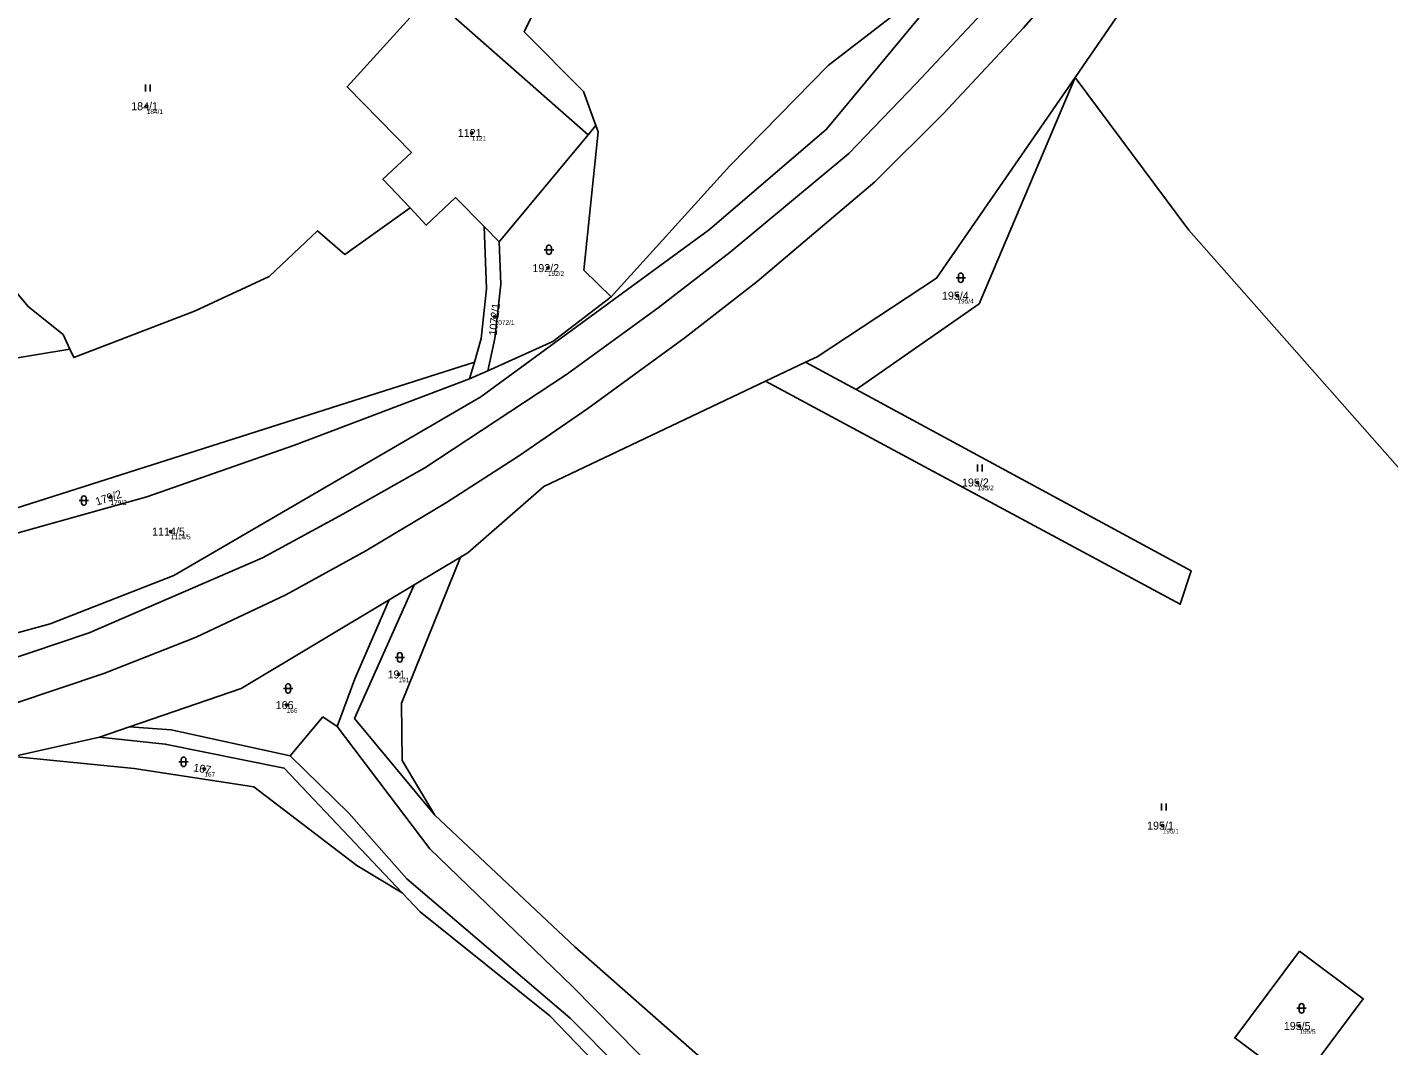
# Model space of a CAD drawing. Extents: x -554500 to -548272, y -1079733 to -1073730.
# Drawn here: x -552544.1 to -552254.7, y -1077027.7 to -1076811.2 of the extents above; entities that cross this region are included whole.
import ezdxf

# ---------------------------------------------------------------- set-up
doc = ezdxf.new("R2010")
doc.units = 0
for name, color, linetype in [('Definiční body', 7, 'Continuous'), ('Hranice parcel', 7, 'Continuous'), ('Parcelní čísla', 7, 'Continuous'), ('Polygon parcely', 7, 'Continuous'), ('Vnitřní kresba', 7, 'Continuous'), ('Značky kultur', 7, 'Continuous')]:
    doc.layers.add(name, color=color, linetype=linetype)

msp = doc.modelspace()

# ---------------------------------------------------------------- linework, layer by layer
at = {"layer": 'Definiční body'}
for centre in [(-552518.66, -1076828.01994), (-552449.6, -1076833.69994), (-552433.42, -1076862.42994), (-552346.39, -1076868.28994), (-552444.74, -1076872.83994), (-552342.14, -1076907.99994), (-552526.36, -1076911.08994), (-552513.57, -1076918.41994), (-552465.15, -1076948.79994), (-552488.94, -1076955.29994), (-552506.43, -1076968.89994), (-552302.8, -1076980.93994), (-552273.75, -1077023.50994)]:
    msp.add_circle(centre, 0.25, dxfattribs=at)
at = {"layer": 'Hranice parcel'}
for p, q in [((-552457.08, -1076805.77), (-552424.83, -1076834.09)), ((-552310.33, -1076805.85), (-552321.39, -1076821.89)), ((-552424.83, -1076834.09), (-552443.81, -1076856.81)), ((-552424.83, -1076834.09), (-552423.2, -1076832.14)), ((-552443.81, -1076856.81), (-552446.97, -1076853.59)), ((-552450.05, -1076885.97), (-552449.01, -1076882.39)), ((-552378.65, -1076882.43), (-552387.19, -1076886.49)), ((-552367.9, -1076888.25), (-552378.65, -1076882.43)), ((-552450.05, -1076885.97), (-552446.18, -1076884.23)), ((-552452, -1076923.9), (-552461.81, -1076929.78)), ((-552461.81, -1076929.78), (-552467.13, -1076932.97)), ((-552522.34, -1076959.95), (-552528.73, -1076962.14)), ((-552528.73, -1076962.14), (-552547.07, -1076966.24))]:
    msp.add_line(p, q, dxfattribs=at)
for points in [[(-552438.83, -1076776.9), (-552426.06, -1076787.21), (-552438.43, -1076812.18), (-552425.84, -1076824.91), (-552423.2, -1076832.14)], [(-552346.57, -1076799.53), (-552374.22, -1076832.9), (-552399.11, -1076854.21), (-552447.65, -1076889.79), (-552512.89, -1076927.79), (-552539.21, -1076938.07), (-552603.07, -1076955.53), (-552606.91, -1076952.69)], [(-552419.95, -1076868.56), (-552394.79, -1076840.7), (-552373.9, -1076819.35), (-552350.45, -1076801.2), (-552346.57, -1076799.53)], [(-552457.08, -1076805.77), (-552458.51, -1076804.49), (-552476.08, -1076823.93), (-552462.42, -1076837.85), (-552468.46, -1076843.54), (-552462.72, -1076849.65)], [(-552321.39, -1076821.89), (-552350.83, -1076864.58), (-552376.22, -1076881.28), (-552378.65, -1076882.43)], [(-552321.39, -1076821.89), (-552341.81, -1076870.01), (-552367.9, -1076888.25)], [(-552214.47, -1076946.82), (-552224.62, -1076936.61), (-552297.2, -1076854.34), (-552321.39, -1076821.89)], [(-552423.2, -1076832.14), (-552422.71, -1076833.48), (-552425.8, -1076862.86), (-552419.95, -1076868.56)], [(-552446.97, -1076853.59), (-552453.02, -1076847.43), (-552459.27, -1076853.31), (-552462.72, -1076849.65)], [(-552462.72, -1076849.65), (-552476.59, -1076859.51), (-552482.38, -1076854.49), (-552492.64, -1076864.2), (-552508.52, -1076871.6), (-552534.18, -1076881.44), (-552534.99, -1076879.69)], [(-552534.99, -1076879.69), (-552536.45, -1076876.51), (-552543.75, -1076870.63), (-552557.16, -1076854.73), (-552574.74, -1076858.68)], [(-552449.01, -1076882.39), (-552447.57, -1076877.4), (-552446.49, -1076866.82), (-552446.97, -1076853.59)], [(-552443.81, -1076856.81), (-552443.41, -1076865.86), (-552444.67, -1076877.42), (-552446.18, -1076884.23)], [(-552446.18, -1076884.23), (-552432.39, -1076878.02), (-552419.95, -1076868.56)], [(-552534.99, -1076879.69), (-552565.54, -1076884.7), (-552574.31, -1076892.6), (-552596.73, -1076899.68), (-552610.12, -1076910.54), (-552662.95, -1076932.83), (-552671.9, -1076938.83)], [(-552612.05, -1076948.89), (-552568.93, -1076920.59), (-552449.01, -1076882.39)], [(-552606.91, -1076952.69), (-552587.97, -1076938.97), (-552565.62, -1076924.94), (-552556.21, -1076921.51), (-552518.61, -1076911.04), (-552487.29, -1076900.06), (-552450.05, -1076885.97)], [(-552387.19, -1076886.49), (-552434.3, -1076908.86), (-552450.44, -1076922.96), (-552452, -1076923.9)], [(-552367.9, -1076888.25), (-552296.74, -1076926.75), (-552299.06, -1076933.88), (-552387.19, -1076886.49)], [(-552457.43, -1076978.68), (-552464.37, -1076967.12), (-552464.53, -1076954.93), (-552452, -1076923.9)], [(-552461.81, -1076929.78), (-552474.5, -1076958.16), (-552457.43, -1076978.68)], [(-552467.13, -1076932.97), (-552498.59, -1076951.8), (-552522.34, -1076959.95)], [(-552478.23, -1076959.85), (-552474.45, -1076949.72), (-552467.13, -1076932.97)], [(-552488.18, -1076966.12), (-552481.23, -1076957.82), (-552478.23, -1076959.85)], [(-552522.34, -1076959.95), (-552513.47, -1076960.55), (-552488.18, -1076966.12)], [(-552003.16, -1077148.87), (-552066.45, -1077133.87), (-552097.39, -1077132.02), (-552117.4, -1077128.2), (-552162.68, -1077124.75), (-552183.65, -1077121.42), (-552235.84, -1077136.49), (-552278.25, -1077120.77), (-552291.51, -1077117.04), (-552315.43, -1077100.3), (-552359.93, -1077070.34), (-552386.3, -1077053.18), (-552404.96, -1077038.74), (-552428.17, -1077015.12), (-552458.54, -1076985.87), (-552478.23, -1076959.85)], [(-552464.37, -1076995.19), (-552489.45, -1076968.7), (-552514.74, -1076963.59), (-552528.73, -1076962.14)], [(-552547.07, -1076966.24), (-552521.34, -1076968.79), (-552495.87, -1076972.7), (-552473.99, -1076989.37), (-552464.37, -1076995.19)], [(-552488.18, -1076966.12), (-552475.72, -1076978.25), (-552463.39, -1076992.24), (-552428.7, -1077021.87), (-552407.66, -1077043.02), (-552379.69, -1077065.86), (-552347.28, -1077090.35), (-552309.72, -1077113.73), (-552291.24, -1077129.35), (-552235.83, -1077188.41), (-552210.35, -1077214.27), (-552151.33, -1077261.82)], [(-552457.43, -1076978.68), (-552427.73, -1077006.67), (-552392.11, -1077037.99), (-552378.85, -1077048.33), (-552297.05, -1077103.87)], [(-552260.41, -1077166.05), (-552293.39, -1077130.79), (-552310.87, -1077116.37), (-552352.02, -1077090.37), (-552410.63, -1077044.59), (-552433.01, -1077021.34), (-552460.53, -1076999.25), (-552464.37, -1076995.19)], [(-552273.72, -1077007.61), (-552260.16, -1077017.73), (-552273.91, -1077036.17), (-552287.48, -1077026.04), (-552273.72, -1077007.61)]]:
    msp.add_lwpolyline(points, dxfattribs=at)
at = {"layer": 'Polygon parcely'}
for points in [[(-551999.3, -1076526.07), (-552010.87, -1076527.63), (-552069.7, -1076539.42), (-552133.32, -1076566.09), (-552182.66, -1076602.14), (-552190.26, -1076610.7), (-552192.81, -1076613.57), (-552196.25, -1076617.44), (-552232.91, -1076658.76), (-552278.63, -1076708.6), (-552281.34, -1076714.84), (-552283.97, -1076720.95), (-552309.19, -1076755.85), (-552313.73, -1076761.03), (-552315.85, -1076763.45), (-552328.64, -1076778.02), (-552330.5, -1076780.14), (-552346.57, -1076799.53), (-552374.22, -1076832.9), (-552399.11, -1076854.21), (-552447.65, -1076889.79), (-552512.89, -1076927.79), (-552539.21, -1076938.07), (-552603.07, -1076955.53)], [(-552557.16, -1076854.73), (-552543.75, -1076870.63), (-552536.45, -1076876.51), (-552534.99, -1076879.69), (-552534.18, -1076881.44), (-552508.52, -1076871.6), (-552492.64, -1076864.2), (-552482.38, -1076854.49), (-552476.59, -1076859.51), (-552462.72, -1076849.65), (-552468.46, -1076843.54), (-552462.42, -1076837.85), (-552476.08, -1076823.93), (-552458.51, -1076804.49), (-552457.08, -1076805.77), (-552455.1, -1076802.88), (-552484.74, -1076783.52), (-552486.79, -1076785.42), (-552511.86, -1076786.78), (-552529.93, -1076790.39), (-552540.74, -1076796.32), (-552547.51, -1076797)], [(-552547.07, -1076966.24), (-552528.73, -1076962.14), (-552522.34, -1076959.95), (-552498.59, -1076951.8), (-552467.13, -1076932.97), (-552461.81, -1076929.78), (-552452, -1076923.9), (-552450.44, -1076922.96), (-552434.3, -1076908.86), (-552387.19, -1076886.49), (-552378.65, -1076882.43), (-552376.22, -1076881.28), (-552350.83, -1076864.58), (-552321.39, -1076821.89), (-552310.33, -1076805.85)], [(-552095.22, -1077044.76), (-552139.39, -1077015.91), (-552159.33, -1077012.39), (-552166.13, -1077004.81), (-552214.47, -1076946.82), (-552224.62, -1076936.61), (-552297.2, -1076854.34), (-552321.39, -1076821.89), (-552341.81, -1076870.01), (-552367.9, -1076888.25), (-552296.74, -1076926.75), (-552299.06, -1076933.88), (-552387.19, -1076886.49), (-552434.3, -1076908.86), (-552450.44, -1076922.96), (-552452, -1076923.9), (-552464.53, -1076954.93), (-552464.37, -1076967.12), (-552457.43, -1076978.68), (-552427.73, -1077006.67), (-552392.11, -1077037.99)], [(-552568.93, -1076920.59), (-552449.01, -1076882.39), (-552447.57, -1076877.4), (-552446.49, -1076866.82), (-552446.97, -1076853.59), (-552453.02, -1076847.43), (-552459.27, -1076853.31), (-552462.72, -1076849.65), (-552476.59, -1076859.51), (-552482.38, -1076854.49), (-552492.64, -1076864.2), (-552508.52, -1076871.6), (-552534.18, -1076881.44), (-552534.99, -1076879.69), (-552565.54, -1076884.7)], [(-552392.11, -1077037.99), (-552427.73, -1077006.67), (-552457.43, -1076978.68), (-552474.5, -1076958.16), (-552461.81, -1076929.78), (-552467.13, -1076932.97), (-552474.45, -1076949.72), (-552478.23, -1076959.85), (-552458.54, -1076985.87), (-552428.17, -1077015.12), (-552404.96, -1077038.74)], [(-552404.96, -1077038.74), (-552428.17, -1077015.12), (-552458.54, -1076985.87), (-552478.23, -1076959.85), (-552481.23, -1076957.82), (-552488.18, -1076966.12), (-552475.72, -1076978.25), (-552463.39, -1076992.24), (-552428.7, -1077021.87), (-552407.66, -1077043.02)], [(-552407.66, -1077043.02), (-552428.7, -1077021.87), (-552463.39, -1076992.24), (-552475.72, -1076978.25), (-552488.18, -1076966.12), (-552513.47, -1076960.55), (-552522.34, -1076959.95), (-552528.73, -1076962.14), (-552514.74, -1076963.59), (-552489.45, -1076968.7), (-552464.37, -1076995.19), (-552460.53, -1076999.25), (-552433.01, -1077021.34), (-552410.63, -1077044.59)], [(-552410.63, -1077044.59), (-552433.01, -1077021.34), (-552460.53, -1076999.25), (-552464.37, -1076995.19), (-552473.99, -1076989.37), (-552495.87, -1076972.7), (-552521.34, -1076968.79), (-552547.07, -1076966.24), (-552598.32, -1076977.69), (-552618.67, -1076982.19), (-552624.65, -1076986.56), (-552641.61, -1077002.14), (-552623.28, -1077019.34), (-552565.77, -1077041.85)]]:
    msp.add_lwpolyline(points, dxfattribs=at)
for points in [[(-552421.26, -1076751.77), (-552438.83, -1076776.9), (-552426.06, -1076787.21), (-552438.43, -1076812.18), (-552425.84, -1076824.91), (-552423.2, -1076832.14), (-552422.71, -1076833.48), (-552425.8, -1076862.86), (-552419.95, -1076868.56), (-552394.79, -1076840.7), (-552373.9, -1076819.35), (-552350.45, -1076801.2), (-552346.57, -1076799.53), (-552330.5, -1076780.14), (-552328.64, -1076778.02), (-552351.68, -1076758.33), (-552363.22, -1076769.03), (-552398.68, -1076730.92), (-552408.48, -1076738.87)], [(-552457.08, -1076805.77), (-552424.83, -1076834.09), (-552423.2, -1076832.14), (-552425.84, -1076824.91), (-552438.43, -1076812.18), (-552426.06, -1076787.21), (-552438.83, -1076776.9), (-552445.87, -1076786.96), (-552448.97, -1076796.82), (-552449.99, -1076804.62), (-552454.33, -1076801.74), (-552455.1, -1076802.88)], [(-552248.38, -1076798.22), (-552279.98, -1076782.94), (-552284.15, -1076791.02), (-552293.63, -1076799.13), (-552298.55, -1076801.8), (-552310.33, -1076805.85), (-552321.39, -1076821.89), (-552297.2, -1076854.34), (-552224.62, -1076936.61), (-552214.47, -1076946.82), (-552210.15, -1076942.51), (-552158.11, -1076990.46), (-552131.22, -1077011.75), (-552097.31, -1076982.58), (-552114.57, -1076960.85), (-552150.87, -1076916.09), (-552159.4, -1076916.41), (-552168.49, -1076909.26), (-552181.49, -1076894.54), (-552192.4, -1076860.69), (-552224.41, -1076812.95), (-552243.29, -1076808.27)], [(-552450.05, -1076885.97), (-552487.29, -1076900.06), (-552518.61, -1076911.04), (-552556.21, -1076921.51), (-552565.62, -1076924.94), (-552587.97, -1076938.97), (-552606.91, -1076952.69), (-552603.07, -1076955.53), (-552539.21, -1076938.07), (-552512.89, -1076927.79), (-552447.65, -1076889.79), (-552399.11, -1076854.21), (-552374.22, -1076832.9), (-552346.57, -1076799.53), (-552350.45, -1076801.2), (-552373.9, -1076819.35), (-552394.79, -1076840.7), (-552419.95, -1076868.56), (-552432.39, -1076878.02), (-552446.18, -1076884.23)], [(-552468.46, -1076843.54), (-552462.72, -1076849.65), (-552459.27, -1076853.31), (-552453.02, -1076847.43), (-552446.97, -1076853.59), (-552443.81, -1076856.81), (-552424.83, -1076834.09), (-552457.08, -1076805.77), (-552458.51, -1076804.49), (-552476.08, -1076823.93), (-552462.42, -1076837.85)], [(-552350.83, -1076864.58), (-552376.22, -1076881.28), (-552378.65, -1076882.43), (-552367.9, -1076888.25), (-552341.81, -1076870.01), (-552321.39, -1076821.89)], [(-552443.41, -1076865.86), (-552444.67, -1076877.42), (-552446.18, -1076884.23), (-552432.39, -1076878.02), (-552419.95, -1076868.56), (-552425.8, -1076862.86), (-552422.71, -1076833.48), (-552423.2, -1076832.14), (-552424.83, -1076834.09), (-552443.81, -1076856.81)], [(-552536.45, -1076876.51), (-552543.75, -1076870.63), (-552557.16, -1076854.73), (-552574.74, -1076858.68), (-552565.82, -1076869.38), (-552565.36, -1076873.21), (-552576.97, -1076874.1), (-552580.41, -1076884.17), (-552597.49, -1076887.01), (-552620.9, -1076895.66), (-552666.84, -1076919.13), (-552682.9, -1076923.94), (-552671.9, -1076938.83), (-552662.95, -1076932.83), (-552610.12, -1076910.54), (-552596.73, -1076899.68), (-552574.31, -1076892.6), (-552565.54, -1076884.7), (-552534.99, -1076879.69)], [(-552446.18, -1076884.23), (-552444.67, -1076877.42), (-552443.41, -1076865.86), (-552443.81, -1076856.81), (-552446.97, -1076853.59), (-552446.49, -1076866.82), (-552447.57, -1076877.4), (-552449.01, -1076882.39), (-552450.05, -1076885.97)], [(-552450.05, -1076885.97), (-552449.01, -1076882.39), (-552568.93, -1076920.59), (-552612.05, -1076948.89), (-552606.91, -1076952.69), (-552587.97, -1076938.97), (-552565.62, -1076924.94), (-552556.21, -1076921.51), (-552518.61, -1076911.04), (-552487.29, -1076900.06)], [(-552387.19, -1076886.49), (-552299.06, -1076933.88), (-552296.74, -1076926.75), (-552367.9, -1076888.25), (-552378.65, -1076882.43)], [(-552461.81, -1076929.78), (-552474.5, -1076958.16), (-552457.43, -1076978.68), (-552464.37, -1076967.12), (-552464.53, -1076954.93), (-552452, -1076923.9)], [(-552498.59, -1076951.8), (-552522.34, -1076959.95), (-552513.47, -1076960.55), (-552488.18, -1076966.12), (-552481.23, -1076957.82), (-552478.23, -1076959.85), (-552474.45, -1076949.72), (-552467.13, -1076932.97)], [(-552495.87, -1076972.7), (-552473.99, -1076989.37), (-552464.37, -1076995.19), (-552489.45, -1076968.7), (-552514.74, -1076963.59), (-552528.73, -1076962.14), (-552547.07, -1076966.24), (-552521.34, -1076968.79)], [(-552273.72, -1077007.61), (-552287.48, -1077026.04), (-552273.91, -1077036.17), (-552260.16, -1077017.73)], [(-552273.72, -1077007.61), (-552260.16, -1077017.73), (-552273.91, -1077036.17), (-552287.48, -1077026.04)]]:
    msp.add_lwpolyline(points, close=True, dxfattribs=at)
at = {"layer": 'Vnitřní kresba'}
for p, q in [((-552318.36, -1076795.36), (-552332.33, -1076811.38)), ((-552339.01, -1076805.96), (-552355.17, -1076823.2)), ((-552349.33, -1076829.58), (-552332.33, -1076811.38)), ((-552355.17, -1076823.2), (-552369.49, -1076838.06)), ((-552363.96, -1076844.11), (-552349.33, -1076829.58)), ((-552369.49, -1076838.06), (-552394.72, -1076859.01)), ((-552388.97, -1076865.3), (-552363.96, -1076844.11)), ((-552394.72, -1076859.01), (-552410.02, -1076870.88)), ((-552404.27, -1076877.17), (-552388.97, -1076865.3)), ((-552429.46, -1076885.07), (-552410.02, -1076870.88)), ((-552404.27, -1076877.17), (-552424.9, -1076892.3)), ((-552459.57, -1076904.91), (-552429.46, -1076885.07)), ((-552424.9, -1076892.3), (-552439.7, -1076902.38)), ((-552439.7, -1076902.38), (-552454.94, -1076912.25)), ((-552477.01, -1076914.75), (-552459.57, -1076904.91)), ((-552454.94, -1076912.25), (-552472.12, -1076922.5)), ((-552494.04, -1076924.04), (-552477.01, -1076914.75)), ((-552494.04, -1076924.04), (-552530.92, -1076939.96)), ((-552472.12, -1076922.5), (-552489.09, -1076931.89)), ((-552508.14, -1076940.89), (-552489.09, -1076931.89)), ((-552530.92, -1076939.96), (-552549.89, -1076946.3)), ((-552527.79, -1076948.61), (-552508.14, -1076940.89)), ((-552546.77, -1076954.94), (-552527.79, -1076948.61))]:
    msp.add_line(p, q, dxfattribs=at)
at = {"layer": 'Značky kultur'}
for p, q in [((-552518.941, -1076824.88), (-552518.941, -1076823.38)), ((-552517.94, -1076824.88), (-552517.94, -1076823.38)), ((-552434.191, -1076858.521), (-552432.189, -1076858.521)), ((-552433.691, -1076858.021), (-552433.691, -1076859.022)), ((-552432.689, -1076859.022), (-552432.689, -1076858.021)), ((-552346.701, -1076864.491), (-552344.699, -1076864.491)), ((-552346.201, -1076863.991), (-552346.201, -1076864.992)), ((-552345.199, -1076864.992), (-552345.199, -1076863.991)), ((-552342.161, -1076905.68), (-552342.161, -1076904.18)), ((-552341.16, -1076905.68), (-552341.16, -1076904.18)), ((-552533.021, -1076911.831), (-552531.019, -1076911.831)), ((-552532.521, -1076911.331), (-552532.521, -1076912.332)), ((-552531.519, -1076912.332), (-552531.519, -1076911.331)), ((-552465.891, -1076945.161), (-552463.889, -1076945.161)), ((-552465.391, -1076944.661), (-552465.391, -1076945.662)), ((-552464.389, -1076945.662), (-552464.389, -1076944.661)), ((-552489.611, -1076951.761), (-552487.609, -1076951.761)), ((-552489.111, -1076951.261), (-552489.111, -1076952.262)), ((-552488.109, -1076952.262), (-552488.109, -1076951.261)), ((-552511.831, -1076967.371), (-552509.829, -1076967.371)), ((-552511.331, -1076966.871), (-552511.331, -1076967.872)), ((-552510.329, -1076967.872), (-552510.329, -1076966.871)), ((-552303.021, -1076977.7), (-552303.021, -1076976.2)), ((-552302.02, -1076977.7), (-552302.02, -1076976.2)), ((-552273.771, -1077019.261), (-552273.771, -1077020.262)), ((-552272.769, -1077020.262), (-552272.769, -1077019.261)), ((-552274.271, -1077019.761), (-552272.269, -1077019.761))]:
    msp.add_line(p, q, dxfattribs=at)
for centre, start, end in [((-552433.19, -1076858.0209), 0, 180), ((-552433.19, -1076859.0209), 180, 359.9878861), ((-552345.7, -1076863.9909), 0, 180), ((-552345.7, -1076864.9909), 180, 359.9878861), ((-552532.02, -1076911.3309), 0, 180), ((-552532.02, -1076912.3309), 180, 359.9878861), ((-552464.89, -1076944.6609), 0, 180), ((-552464.89, -1076945.6609), 180, 359.9878861), ((-552488.61, -1076951.2609), 0, 180), ((-552488.61, -1076952.2609), 180, 359.9878861), ((-552510.83, -1076966.8709), 0, 180), ((-552510.83, -1076967.8709), 180, 359.9878861), ((-552273.27, -1077019.2609), 0, 180), ((-552273.27, -1077020.2609), 180, 359.9878861)]:
    msp.add_arc(centre, 0.5, start, end, dxfattribs=at)

# ---------------------------------------------------------------- texts
at = {"layer": 'Definiční body'}
for s, p in [('184/1', (-552518.66, -1076829.676)), ('1121', (-552449.6, -1076835.356)), ('192/2', (-552433.42, -1076864.086)), ('195/4', (-552346.39, -1076869.946)), ('1072/1', (-552444.74, -1076874.496)), ('195/2', (-552342.14, -1076909.656)), ('179/2', (-552526.36, -1076912.746)), ('1114/5', (-552513.57, -1076920.076)), ('191', (-552465.15, -1076950.456)), ('166', (-552488.94, -1076956.956)), ('167', (-552506.43, -1076970.556)), ('195/1', (-552302.8, -1076982.596)), ('195/5', (-552273.75, -1077025.166))]:
    msp.add_text(s, height=0.999996, dxfattribs=at).set_placement(p)
at = {"layer": 'Parcelní čísla'}
for s, p in [('184/1', (-552521.958, -1076828.87)), ('1121', (-552452.574, -1076834.55)), ('192/2', (-552436.718, -1076863.28)), ('195/4', (-552349.688, -1076869.14)), ('195/2', (-552345.438, -1076908.85)), ('1114/5', (-552517.517, -1076919.27)), ('191', (-552467.475, -1076949.65)), ('166', (-552491.265, -1076956.15)), ('195/1', (-552306.098, -1076981.79)), ('195/5', (-552277.048, -1077024.36))]:
    msp.add_text(s, height=1.699998, dxfattribs=at).set_placement(p)
for s, rotation, p in [('1072/1', 84, (-552444.307, -1076876.854)), ('179/2', 18, (-552529.234, -1076912.917)), ('167', 351, (-552508.859, -1076969.375))]:
    msp.add_text(s, height=1.699998, rotation=rotation, dxfattribs=at).set_placement(p)

doc.saveas('drawing.dxf')
